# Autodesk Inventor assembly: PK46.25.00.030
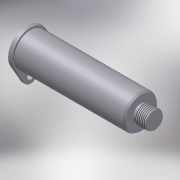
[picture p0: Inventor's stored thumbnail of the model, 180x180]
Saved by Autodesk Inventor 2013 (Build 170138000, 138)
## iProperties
Created: 2005-05
Part Number: PK46.25.00.030
Document SubType Name: Assembly
Designer: PVitaliy
Manufacturer: Standard
Standards Organization: Custom
Author: PVitaliy
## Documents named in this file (3)
- C:\Product Design Suite 2013 Test Drive\Dynamic Simulation\Workspace\Assy, Chassis, Front\PK46.25.00.030.iam
- C:\Product Design Suite 2013 Test Drive\Dynamic Simulation\Workspace\Assy, Chassis, Front\PK46.25.00.004.ipt
- C:\Product Design Suite 2013 Test Drive\Dynamic Simulation\Workspace\Assy, Chassis, Front\PK46.25.00.002.ipt
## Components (2 placed, 2 different names)
1. PK46.25.00.004:1 — Вставка:1
2. PK46.25.00.002:1 — Вставка:1, Совмещение:1
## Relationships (2: Insert 1, Mate 1)
- Вставка:1 [Insert]: PK46.25.00.004:1 ↔ PK46.25.00.002:1
- Совмещение:1 [Mate]: PK46.25.00.002:1
